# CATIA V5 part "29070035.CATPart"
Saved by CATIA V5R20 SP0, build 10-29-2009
Part number: 29070035
Definition: NONE
Nomenclature: 29070035
Source: Unknown
Description: 29070035
Bounding box of the stored display mesh (mm): x -17.5 to 44.548, y -49 to 83.548, z -39 to 39
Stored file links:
  C:\Users\Utente\Desktop\IO LAVORO\3D X SITO CF\X SITO\PLASTICA\RF1\29070035.CATPart
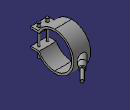
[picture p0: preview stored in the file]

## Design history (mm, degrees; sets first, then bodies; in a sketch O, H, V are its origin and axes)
Body1 "29070035" (main body)
  Solid1: solid without history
